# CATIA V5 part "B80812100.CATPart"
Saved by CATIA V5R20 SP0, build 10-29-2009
Part number: B80812100
Revision: 3
Definition: design
Nomenclature: B80812100
Source: made
Description: NOT SPECIFIED
Bounding box of the stored display mesh (mm): x -8 to 8, y -8 to 8, z 0 to 100
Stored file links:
  C:\Users\Raffaele\Desktop\3D X SITO CF\BOLEX\4-PILLAR REF 808\B80812100.CATPart
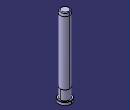
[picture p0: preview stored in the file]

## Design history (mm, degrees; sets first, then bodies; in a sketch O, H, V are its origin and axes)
Body1 "MANIFOLD_SOLID_BREP #450" (main body)
  Solid1: solid without history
